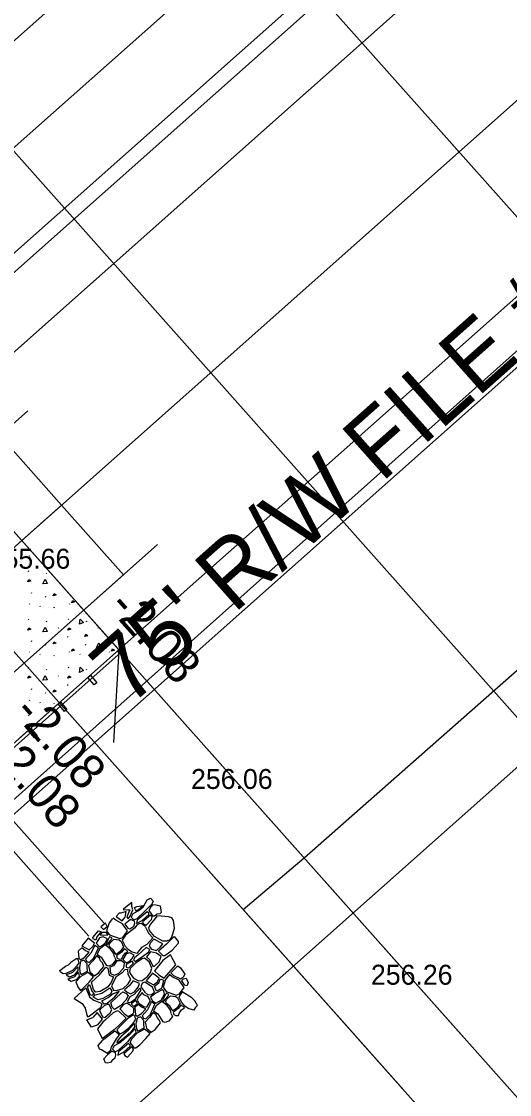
# Model space of a CAD drawing. Extents: x 49683 to 58852, y 49525 to 54803.
# Drawn here: x 53475.3 to 53548.7, y 51366.9 to 51528.4 of the extents above; entities that cross this region are included whole.
import ezdxf

# ---------------------------------------------------------------- set-up
doc = ezdxf.new("R2010")
doc.units = 0
for name, color, linetype in [('Level 1', 7, 'Continuous'), ('Level 11', 7, 'Continuous'), ('Level 13', 7, 'Continuous'), ('Level 15', 7, 'Continuous'), ('Level 16', 7, 'Continuous'), ('Level 19', 7, 'Continuous'), ('Level 20', 7, 'Continuous'), ('Level 25', 7, 'Continuous'), ('Level 27', 7, 'Continuous'), ('Level 29', 7, 'Continuous'), ('Level 3', 7, 'Continuous'), ('Level 32', 7, 'Continuous'), ('Level 33', 7, 'Continuous'), ('Level 5', 7, 'Continuous'), ('Level 50', 7, 'Continuous'), ('Level 53', 7, 'Continuous'), ('Level 61', 7, 'Continuous'), ('Level 63', 7, 'Continuous'), ('Level 8', 7, 'Continuous')]:
    doc.layers.add(name, color=color, linetype=linetype)

msp = doc.modelspace()

# ---------------------------------------------------------------- linework, layer by layer
at = {"layer": 'Level 1'}
msp.add_line((52544.81, 50683.3), (55534.58, 53340.86), dxfattribs=at)
at = {"layer": 'Level 11'}
msp.add_line((53245.86, 51207.55), (53944.24, 51830.77), dxfattribs=at)
at = {"layer": 'Level 13'}
msp.add_line((53681.55, 51593.39), (53435.6, 51374.77), dxfattribs=at)
at = {"layer": 'Level 15'}
for p, q in [((53460.73, 51466.68), (53909.18, 51865.3)), ((53938.41, 51832.41), (53489.97, 51433.79)), ((53460.73, 51466.68), (53489.97, 51433.79)), ((53476.47, 51448), (53476.52, 51447.91)), ((53476.36, 51445.58), (53476.42, 51445.71)), ((53479.07, 51445.26), (53479.13, 51445.39)), ((53476.82, 51442.31), (53476.88, 51442.43)), ((53478.93, 51441.74), (53478.99, 51441.86)), ((53476.47, 51440.75), (53476.52, 51440.67)), ((53478.08, 51440.4), (53478.14, 51440.32)), ((53480.2, 51440.13), (53480.25, 51440.25)), ((53482.47, 51440.75), (53482.52, 51440.67)), ((53484.08, 51440.4), (53484.14, 51440.32)), ((53476.36, 51438.34), (53476.42, 51438.46)), ((53482.36, 51438.34), (53482.42, 51438.46)), ((53479.07, 51438.02), (53479.13, 51438.14)), ((53480.81, 51437.13), (53480.86, 51437.05)), ((53485.07, 51438.02), (53485.13, 51438.14)), ((53486.81, 51437.13), (53486.86, 51437.05)), ((53476.82, 51435.06), (53476.88, 51435.19)), ((53482.21, 51435.8), (53482.22, 51435.68)), ((53488.21, 51435.77), (53488.22, 51435.68)), ((53489.97, 51433.79), (53475.02, 51420.51)), ((53476.47, 51433.51), (53476.52, 51433.43)), ((53478.93, 51434.5), (53478.99, 51434.62)), ((53482.47, 51433.51), (53482.52, 51433.43)), ((53484.93, 51434.5), (53484.99, 51434.62)), ((53488.47, 51433.51), (53488.52, 51433.43)), ((53489.97, 51433.79), (53489.14, 51419.82)), ((53478.08, 51433.16), (53478.14, 51433.07)), ((53480.2, 51432.89), (53480.25, 51433.01)), ((53484.08, 51433.16), (53484.14, 51433.07)), ((53486.2, 51432.89), (53486.25, 51433.01)), ((53476.36, 51431.1), (53476.42, 51431.22)), ((53479.07, 51430.78), (53479.13, 51430.9)), ((53482.36, 51431.1), (53482.42, 51431.22)), ((53485.07, 51430.78), (53485.13, 51430.9)), ((53480.81, 51429.89), (53480.86, 51429.81)), ((53482.21, 51428.56), (53482.22, 51428.43)), ((53476.82, 51427.82), (53476.88, 51427.95)), ((53478.93, 51427.25), (53478.99, 51427.38)), ((53476.47, 51426.27), (53476.52, 51426.18)), ((53478.08, 51425.91), (53478.14, 51425.83)), ((53480.2, 51425.64), (53480.25, 51425.77)), ((53476.36, 51423.85), (53476.42, 51423.98))]:
    msp.add_line(p, q, dxfattribs=at)
for points in [[(53476.26, 51444.01), (53476.43, 51444.36), (53476.71, 51444.15), (53476.26, 51444.01)], [(53478.52, 51443.72), (53478.89, 51444.43), (53479.19, 51443.78), (53478.53, 51443.72)], [(53480.08, 51441.91), (53480.24, 51442.25), (53480.52, 51442.05), (53480.08, 51441.91)], [(53482.85, 51440.85), (53483.02, 51441.2), (53483.3, 51440.99), (53482.85, 51440.85)], [(53484.03, 51437.63), (53484.14, 51438.42), (53484.64, 51437.91), (53484.04, 51437.64)], [(53476.26, 51436.77), (53476.43, 51437.12), (53476.71, 51436.91), (53476.26, 51436.77)], [(53478.52, 51436.48), (53478.89, 51437.19), (53479.19, 51436.54), (53478.53, 51436.48)], [(53482.26, 51436.77), (53482.43, 51437.12), (53482.71, 51436.91), (53482.26, 51436.77)], [(53480.08, 51434.67), (53480.24, 51435.01), (53480.52, 51434.8), (53480.08, 51434.67)], [(53484.82, 51435.78), (53484.98, 51436.13), (53485.26, 51435.92), (53484.82, 51435.78)], [(53482.85, 51433.61), (53483.02, 51433.95), (53483.3, 51433.75), (53482.85, 51433.61)], [(53486.58, 51434.15), (53486.96, 51434.86), (53487.25, 51434.21), (53486.6, 51434.15)], [(53488.85, 51433.61), (53489.02, 51433.95), (53489.3, 51433.75), (53488.85, 51433.61)], [(53484.03, 51430.39), (53484.14, 51431.18), (53484.64, 51430.67), (53484.04, 51430.39)], [(53476.26, 51429.53), (53476.43, 51429.88), (53476.71, 51429.67), (53476.26, 51429.53)], [(53478.52, 51429.24), (53478.89, 51429.95), (53479.19, 51429.29), (53478.53, 51429.24)], [(53482.26, 51429.53), (53482.43, 51429.88), (53482.71, 51429.67), (53482.26, 51429.53)], [(53480.08, 51427.42), (53480.24, 51427.77), (53480.52, 51427.56), (53480.08, 51427.42)], [(53476.26, 51422.29), (53476.43, 51422.63), (53476.71, 51422.42), (53476.26, 51422.29)]]:
    msp.add_lwpolyline(points, dxfattribs=at)
at = {"layer": 'Level 16'}
for p, q in [((53490.99, 51395.05), (53490.58, 51394.7)), ((53490.58, 51394.7), (53491.31, 51394.67)), ((53491.91, 51395.78), (53490.99, 51395.05)), ((53491.31, 51394.67), (53491.59, 51394.67)), ((53491.59, 51394.67), (53491.47, 51394.29)), ((53491.63, 51393.69), (53492.04, 51394.67)), ((53491.88, 51395.18), (53491.91, 51395.78)), ((53492.04, 51394.67), (53491.88, 51395.18)), ((53489.98, 51394.13), (53489.54, 51393.66)), ((53489.54, 51393.66), (53490.43, 51393)), ((53490.24, 51394.13), (53489.98, 51394.13)), ((53491.03, 51394.39), (53490.24, 51394.13)), ((53490.43, 51393), (53490.9, 51393.53)), ((53490.9, 51393.53), (53491.03, 51394.39)), ((53491.47, 51394.29), (53491.15, 51393.6)), ((53491.15, 51393.6), (53491.37, 51393.31)), ((53491.37, 51393.31), (53491.63, 51393.69)), ((53487.12, 51390.83), (53487.5, 51391.3)), ((53487.62, 51390.8), (53487.12, 51390.83)), ((53487.5, 51391.3), (53487.97, 51391.3)), ((53488.28, 51390.83), (53487.62, 51390.8)), ((53487.97, 51391.3), (53488.28, 51390.83))]:
    msp.add_line(p, q, dxfattribs=at)
for points in [[(53493.59, 51395.04), (53494.22, 51396.16), (53494.73, 51396.4), (53495.11, 51395.98), (53494.89, 51395.51), (53493.83, 51394.39)], [(53493.59, 51395.04), (53493.01, 51394.55), (53492.06, 51394.04), (53491.8, 51393.54), (53492.22, 51393.14), (53492.69, 51393.35), (53493.83, 51394.39)], [(53492.39, 51394.78), (53492.34, 51394.88), (53492.28, 51395), (53492.71, 51395.16), (53493.61, 51395.29)], [(53492.39, 51394.76), (53492.45, 51394.63), (53492.5, 51394.51), (53492.9, 51394.71), (53493.61, 51395.29)], [(53493.57, 51395.26), (53493.5, 51395.2)], [(53495.08, 51395.45), (53494.74, 51395.09), (53494.44, 51394.55), (53494.8, 51394.03), (53495.01, 51393.75), (53495.32, 51393.73), (53495.66, 51394)], [(53495.08, 51395.45), (53495.56, 51395.42), (53496.16, 51395.24), (53496.26, 51394.62), (53496.3, 51394.27), (53496.09, 51394.04), (53495.66, 51394)], [(53489, 51393.34), (53488.47, 51392.7), (53488.11, 51391.51), (53488.54, 51390.89), (53490.08, 51390.32), (53490.56, 51390.51), (53491.26, 51391.5), (53490.49, 51392.57), (53489.48, 51393.1), (53489.11, 51393.39)], [(53497.32, 51390.02), (53497.14, 51389.94), (53496.55, 51389.94), (53495.29, 51390.63), (53494.58, 51391.55), (53494.46, 51392), (53494.7, 51392.45), (53495.4, 51393.28)], [(53495.41, 51393.3), (53495.77, 51393.74)], [(53497.32, 51390.02), (53497.52, 51390.1), (53497.93, 51390.52), (53498.32, 51391.9), (53498.16, 51393.06), (53497.92, 51393.46), (53497.44, 51393.6), (53495.77, 51393.74)], [(53493.91, 51392.17), (53493.37, 51392.58), (53493.01, 51392.57), (53492.66, 51392.36), (53492.31, 51391.92), (53490.96, 51390.82), (53490.45, 51390.08), (53490.92, 51389.18)], [(53493.93, 51392.14), (53494.42, 51391.12), (53495.07, 51390.45), (53494.17, 51389.42), (53493.38, 51388.97), (53492.65, 51388.06), (53491.86, 51388.31), (53491.37, 51388.68), (53490.95, 51389.16)], [(53497.12, 51389.49), (53498.28, 51390.62), (53498.87, 51389.87), (53498.85, 51389.58), (53497.95, 51388.57)], [(53489.31, 51387.56), (53489.21, 51388.06), (53488.71, 51388.75), (53487.9, 51389.39), (53487.03, 51388.74), (53486.67, 51387.97), (53487.3, 51387.52), (53488.06, 51386.33)], [(53497.12, 51389.49), (53495.89, 51388.42), (53496.58, 51387.77), (53496.87, 51387.77), (53497.95, 51388.57)], [(53483, 51385.51), (53483.74, 51386.32), (53483.96, 51386.7), (53483.82, 51387.16), (53483.62, 51387.34), (53482.74, 51386.75), (53482.37, 51386.4)], [(53489.32, 51387.53), (53489.48, 51387.13), (53488.95, 51386.4), (53488.41, 51386.2), (53488.09, 51386.3)], [(53483, 51385.51), (53481.99, 51385.09), (53481.56, 51385), (53481.17, 51385.29), (53481.07, 51385.54), (53481.93, 51386.18), (53482.37, 51386.4)], [(53483.25, 51384.82), (53482.53, 51384.54), (53482.26, 51384.69), (53482.08, 51384.92), (53483.02, 51385.25)], [(53483.02, 51385.25), (53483.76, 51386.06), (53483.8, 51385.53), (53483.25, 51384.82)], [(53483.51, 51384.14), (53484.03, 51384.69), (53484, 51384.99), (53483.85, 51385.25), (53483.23, 51384.56)], [(53484.17, 51382.54), (53484.57, 51382.87), (53485.5, 51383.78), (53486.13, 51384.56), (53485.3, 51385.21), (53484.22, 51384.61), (53483.47, 51383.83)], [(53497.77, 51385.18), (53498.82, 51386.24), (53499.2, 51385.94), (53499.85, 51384.98), (53499.61, 51384.52)], [(53497.77, 51385.18), (53498.17, 51384.79), (53499.2, 51384.25), (53499.63, 51384.54)], [(53483.51, 51384.14), (53482.8, 51383.87), (53482.53, 51384.02), (53482.35, 51384.25), (53483.23, 51384.56)], [(53483.47, 51383.83), (53483.81, 51382.95), (53484.17, 51382.54)], [(53499.68, 51384.26), (53499.35, 51383.99), (53499.79, 51383.38), (53500.24, 51383.25)], [(53499.68, 51384.26), (53500.08, 51384.39), (53500.36, 51383.7), (53500.24, 51383.25)], [(53485, 51382.91), (53483.23, 51381.29), (53484.45, 51380.56), (53484.87, 51379.87), (53485.11, 51378.8), (53485.29, 51378.56), (53485.56, 51378.64)], [(53485, 51382.91), (53485.55, 51381.57), (53486.17, 51381.05), (53487.18, 51380.66), (53487.39, 51380.44), (53487.17, 51379.93), (53485.56, 51378.64)], [(53499.49, 51382.33), (53498.96, 51381.57), (53499.44, 51380.67)], [(53501.45, 51379.9), (53501.76, 51380.24), (53501.38, 51380.98), (53500.94, 51381.4), (53499.49, 51382.33)], [(53497.82, 51379.05), (53497.72, 51379.55), (53497.22, 51380.24), (53496.41, 51380.88), (53495.54, 51380.23), (53495.18, 51379.46), (53495.81, 51379), (53496.57, 51377.81)], [(53501.45, 51379.9), (53501.17, 51379.54), (53500.37, 51379.8), (53499.89, 51380.17), (53499.46, 51380.65)], [(53486.81, 51377.35), (53487.48, 51378.2), (53486.68, 51379.21), (53486.03, 51378.43)], [(53489.34, 51376.72), (53490.03, 51377.35), (53491.07, 51378.37), (53490, 51379.35), (53489.68, 51379.44), (53489.08, 51379.15), (53487.94, 51378.11)], [(53497.83, 51379.02), (53498, 51378.62), (53497.46, 51377.89), (53496.92, 51377.69), (53496.6, 51377.79)], [(53486.81, 51377.35), (53485.84, 51377.01), (53485.15, 51378.09), (53486.03, 51378.43)], [(53487.92, 51378.09), (53487.55, 51377.77), (53486.72, 51376.74), (53487.43, 51375.27), (53489.32, 51376.7)], [(53490.37, 51375.7), (53491.4, 51376.6), (53492.27, 51377.54), (53492.31, 51377.02), (53491.8, 51376.36), (53491.28, 51375.88), (53490.69, 51375.36)], [(53488.14, 51373.1), (53488.71, 51373.47), (53488.85, 51374), (53489.6, 51375.22), (53490.03, 51375.82), (53489.36, 51376.4), (53487.47, 51374.99)], [(53490.8, 51375.22), (53490.2, 51374.71), (53489.24, 51374.2), (53488.98, 51373.7), (53489.4, 51373.3), (53489.88, 51373.51), (53491.25, 51374.77)], [(53490.34, 51375.68), (53489.83, 51375.08), (53489.63, 51374.79), (53489.68, 51374.66), (53490.09, 51374.87), (53490.67, 51375.35)], [(53491.28, 51374.79), (53491.82, 51375.42), (53492.54, 51376.18), (53492.51, 51376.48), (53492.36, 51376.74), (53491.55, 51375.83), (53490.82, 51375.25)], [(53488.14, 51373.1), (53487.35, 51373.59), (53487.04, 51373.67), (53486.82, 51374.26), (53487.47, 51374.99)], [(53491.26, 51372.5), (53492.04, 51373.36), (53492.16, 51373.74), (53491.91, 51374.03), (53490.71, 51373), (53490.83, 51372.73), (53491.26, 51372.5)], [(53488.98, 51372.09), (53488.68, 51371.68), (53488.24, 51371.58), (53487.93, 51371.65), (53487.71, 51372.25), (53488.25, 51372.85)], [(53488.98, 51372.09), (53489.4, 51372.37), (53489.52, 51372.81), (53489.46, 51373.12), (53488.87, 51373.36), (53488.25, 51372.85)]]:
    msp.add_lwpolyline(points, dxfattribs=at)
for points in [[(53490.84, 51392.51), (53491.28, 51391.89), (53491.6, 51391.8), (53492.21, 51392.21), (53492.34, 51392.65), (53492.28, 51392.96), (53491.69, 51393.21)], [(53494.23, 51394.37), (53492.73, 51393.12), (53492.59, 51392.62), (53493.47, 51393.05), (53494.48, 51393.97), (53494.47, 51394.13)], [(53494.73, 51393.87), (53493.53, 51392.84), (53493.65, 51392.57), (53494.08, 51392.34), (53494.86, 51393.2), (53494.97, 51393.58)], [(53487.31, 51391.42), (53486.65, 51390.59), (53486.5, 51390.1), (53486.09, 51390.29), (53486.05, 51390.51), (53486.87, 51391.52)], [(53487.93, 51392.63), (53487.24, 51392.09), (53487.65, 51391.7), (53488.2, 51392.16)], [(53485.34, 51390.41), (53484.37, 51389.24), (53485.47, 51388.63), (53486.06, 51389.12), (53486.3, 51389.64)], [(53488.23, 51390.27), (53487.57, 51390.59), (53487.04, 51390.46), (53486.55, 51389.62), (53487.04, 51389.11), (53487.57, 51389.38), (53487.92, 51389.76)], [(53488.55, 51390.6), (53488.01, 51389.5), (53488.19, 51389.44), (53488.79, 51390.14), (53488.97, 51390.43)], [(53490.66, 51389.11), (53490.16, 51388.38), (53489.56, 51387.95), (53489.12, 51388.66), (53488.55, 51389.13), (53488.49, 51389.42), (53488.67, 51389.72), (53489.2, 51390.23), (53490.02, 51390.12), (53490.28, 51389.91)], [(53496.55, 51389.56), (53495.21, 51390.23), (53494.64, 51389.64), (53494.51, 51389.18), (53494.88, 51388.73), (53495.61, 51388.56), (53496.22, 51389.09)], [(53484.37, 51388.94), (53483.82, 51388.46), (53483.95, 51387.36), (53484.19, 51387.15), (53484.83, 51387.54), (53485.5, 51388.26), (53484.95, 51388.49)], [(53486.36, 51389.3), (53485.73, 51388.14), (53484.94, 51387.23), (53485.13, 51386.86), (53485.48, 51386.75), (53486.18, 51387.44), (53486.87, 51388.96)], [(53490.8, 51388.86), (53490.37, 51388.3), (53489.59, 51387.72), (53489.7, 51387.39), (53490.02, 51387.24), (53490.41, 51387.26), (53490.54, 51387.64), (53490.88, 51388.13), (53491.3, 51388.4)], [(53492.24, 51387.83), (53491.58, 51388.16), (53491.05, 51388.02), (53490.56, 51387.18), (53491.05, 51386.68), (53491.58, 51386.94), (53491.93, 51387.33)], [(53494.63, 51388.67), (53494.05, 51388.99), (53492.83, 51387.84), (53492.36, 51387.47), (53492.17, 51387.15), (53492.42, 51386.9), (53493.51, 51387.64), (53494.44, 51388.33)], [(53496.3, 51387.65), (53495.61, 51388.14), (53494.72, 51388.34), (53494.12, 51387.57), (53494.63, 51387.11), (53495.08, 51386.16), (53495.31, 51386.16), (53495.99, 51386.84)], [(53484.7, 51387.08), (53484.19, 51386.86), (53484.01, 51386.03), (53484.09, 51385.26), (53484.27, 51384.92), (53485.25, 51385.4), (53485.18, 51385.98), (53485.2, 51386.52)], [(53486.57, 51387.72), (53486.05, 51386.99), (53485.38, 51386.27), (53485.59, 51385.34), (53486.3, 51384.73), (53486.91, 51385.17), (53487.71, 51386.14), (53487.47, 51386.69), (53487.18, 51386.98), (53487.04, 51387.37)], [(53489.66, 51386.99), (53489.13, 51386.22), (53488.6, 51386.01), (53488.7, 51385.06), (53489.26, 51384.84), (53489.9, 51385.08), (53490.7, 51385.92), (53490.79, 51386.62), (53490.33, 51387)], [(53491.93, 51386.95), (53491.05, 51386.41), (53491.07, 51386.05), (53491.45, 51385.95), (53492.15, 51386.65)], [(53493.83, 51387.36), (53493.48, 51387.29), (53492.41, 51386.6), (53491.63, 51385.82), (53491.54, 51385.37), (53491.66, 51385.05), (53492.15, 51384.36), (53492.91, 51383.97), (53493.48, 51384.04), (53494.24, 51384.62), (53494.69, 51385.2), (53494.89, 51385.86), (53494.51, 51386.83)], [(53497.73, 51387.88), (53496.59, 51387.05), (53495.3, 51385.45), (53495.97, 51384.85), (53496.79, 51384.35), (53498.54, 51386.38)], [(53488.01, 51386.05), (53488.28, 51385.88), (53488.5, 51384.82), (53489.17, 51384.56), (53488.77, 51383.7), (53488.24, 51383.04), (53487.12, 51382.36), (53486.48, 51382.25), (53486.12, 51382.67), (53485.83, 51383.75), (53487.05, 51384.86)], [(53490.87, 51385.65), (53490.47, 51385.15), (53489.53, 51384.57), (53488.83, 51383.23), (53489.17, 51382.59), (53489.61, 51382.51), (53490.59, 51382.84), (53491.33, 51383.52), (53491.75, 51384.17), (53491.35, 51384.91), (53491.31, 51385.67)], [(53495.03, 51385.13), (53494.06, 51383.96), (53495.16, 51383.35), (53495.75, 51383.84), (53496, 51384.36)], [(53499.77, 51382.99), (53499, 51384.06), (53497.99, 51384.59), (53497.58, 51384.91), (53496.98, 51384.19), (53496.62, 51383), (53497.05, 51382.37), (53498.59, 51381.81), (53499.07, 51382)], [(53485.53, 51383.4), (53485.91, 51382.41), (53486.24, 51382.03), (53485.87, 51381.77), (53485.66, 51381.85), (53485.22, 51383.08)], [(53492.11, 51383.98), (53491.51, 51383.24), (53490.81, 51382.62), (53491.21, 51382.26), (53491.69, 51382.01), (53492.3, 51382.33), (53492.85, 51383), (53493.07, 51383.56)], [(53495.33, 51382.27), (53495.02, 51383.03), (53493.85, 51383.76), (53493.46, 51383.61), (53493.26, 51383.09), (53493.84, 51382.25), (53494.32, 51381.84), (53494.86, 51381.92)], [(53496.23, 51384.25), (53496.66, 51384.09), (53496.38, 51382.8), (53495.63, 51382.42), (53495.3, 51383.19), (53495.95, 51383.67)], [(53488.61, 51382.94), (53488.91, 51382.41), (53488.68, 51381.94), (53487.56, 51381.33), (53486.83, 51381.13), (53486.07, 51381.49), (53486.37, 51381.85), (53487.37, 51382.13)], [(53490.02, 51382.38), (53489.11, 51382.02), (53488.4, 51381.48), (53487.34, 51380.92), (53487.7, 51380.52), (53488.18, 51380.6), (53489.36, 51381.55)], [(53490.55, 51382.32), (53491.05, 51382.06), (53491.34, 51381.7), (53491.01, 51381.07), (53490.18, 51380.21), (53489.28, 51379.64), (53488.95, 51380.03), (53488.74, 51380.64), (53489.71, 51381.54)], [(53493.1, 51382.87), (53492.26, 51381.92), (53491.57, 51381.49), (53491.26, 51380.86), (53491.5, 51380.67), (53491.82, 51380.79), (53492.48, 51381.3), (53493.3, 51382.61)], [(53494.69, 51380.95), (53494.34, 51381.55), (53493.73, 51381.84), (53493.46, 51382.19), (53492.87, 51381.48), (53492.73, 51381.05), (53492.95, 51380.63), (53493.73, 51380.1), (53494.17, 51380.03)], [(53496.49, 51382.64), (53495.52, 51382.12), (53494.7, 51381.49), (53495, 51380.94), (53495.53, 51380.61), (53496.31, 51381.08), (53496.82, 51381.95), (53496.74, 51382.48)], [(53497.06, 51382.09), (53496.52, 51380.99), (53496.7, 51380.93), (53497.31, 51381.63), (53497.48, 51381.92)], [(53499.17, 51380.6), (53498.68, 51379.86), (53498.07, 51379.44), (53497.63, 51380.15), (53497.06, 51380.62), (53497, 51380.9), (53497.18, 51381.21), (53497.71, 51381.71), (53498.53, 51381.6), (53498.79, 51381.4)], [(53488.43, 51380.46), (53487.78, 51380.24), (53487.12, 51379.64), (53487.03, 51379.5), (53487.49, 51378.53), (53487.83, 51378.44), (53488.64, 51379.15), (53488.89, 51379.58)], [(53492.2, 51379.21), (53492.18, 51379.79), (53491.67, 51380.29), (53491.12, 51380.63), (53490.59, 51380.35), (53490.12, 51379.74), (53490.74, 51379.03), (53491.33, 51378.6), (53491.96, 51378.93)], [(53492.48, 51381.03), (53491.79, 51380.49), (53492.2, 51380.1), (53492.75, 51380.56)], [(53492.88, 51380.43), (53492.33, 51379.95), (53492.47, 51378.85), (53492.7, 51378.64), (53493.34, 51379.03), (53494.01, 51379.75), (53493.46, 51379.98)], [(53494.87, 51380.79), (53494.24, 51379.62), (53493.45, 51378.72), (53493.64, 51378.35), (53494, 51378.24), (53494.69, 51378.93), (53495.38, 51380.45)], [(53499.31, 51380.35), (53498.88, 51379.79), (53498.1, 51379.2), (53498.22, 51378.88), (53498.53, 51378.73), (53498.92, 51378.74), (53499.06, 51379.13), (53499.39, 51379.62), (53499.81, 51379.89)], [(53492.13, 51378.83), (53491.25, 51378.24), (53490.34, 51377.37), (53489.64, 51376.6), (53489.85, 51376.26), (53490.15, 51376), (53490.56, 51376.17), (53491.4, 51376.87), (53492.25, 51377.81), (53492.48, 51378.19), (53492.33, 51378.65)], [(53493.21, 51378.57), (53492.7, 51378.35), (53492.52, 51377.52), (53492.6, 51376.75), (53492.79, 51376.41), (53493.76, 51376.89), (53493.69, 51377.47), (53493.72, 51378)], [(53495.08, 51379.21), (53494.57, 51378.47), (53493.89, 51377.76), (53494.11, 51376.83), (53494.81, 51376.22), (53495.42, 51376.65), (53496.22, 51377.63), (53495.98, 51378.17), (53495.69, 51378.46), (53495.55, 51378.86)], [(53494.64, 51376.05), (53493.81, 51376.7), (53492.73, 51376.1), (53491.92, 51375.25), (53491.62, 51374.71), (53491.98, 51374.19), (53492.19, 51373.91), (53492.5, 51373.89), (53493.09, 51374.36), (53494.01, 51375.27)], [(53491.41, 51374.53), (53489.91, 51373.28), (53489.78, 51372.78), (53490.65, 51373.21), (53491.67, 51374.13), (53491.65, 51374.29)]]:
    msp.add_lwpolyline(points, close=True, dxfattribs=at)
at = {"layer": 'Level 19'}
for p, q in [((52714.15, 50773.62), (54181.77, 52078.16)), ((53541.12, 51508.7), (53538.46, 51511.69))]:
    msp.add_line(p, q, dxfattribs=at)
at = {"layer": 'Level 20'}
for p, q in [((52704.85, 50784.08), (53476.26, 51469.77)), ((52723.45, 50763.15), (53495.78, 51449.66))]:
    msp.add_line(p, q, dxfattribs=at)
at = {"layer": 'Level 27'}
for p, q in [((53467.54, 51413.86), (53489.97, 51433.79)), ((53467.88, 51413.49), (53490.3, 51433.42))]:
    msp.add_line(p, q, dxfattribs=at)
for points in [[(53491.12, 51432.8), (53490.74, 51432.48), (53489.77, 51433.63), (53490.16, 51433.95)], [(53486.63, 51428.82), (53486.25, 51428.5), (53485.29, 51429.65), (53485.67, 51429.97)], [(53482.15, 51424.83), (53481.77, 51424.51), (53480.8, 51425.66), (53481.19, 51425.98)], [(53477.67, 51420.84), (53477.28, 51420.52), (53476.32, 51421.67), (53476.7, 51422)]]:
    msp.add_lwpolyline(points, close=True, dxfattribs=at)
at = {"layer": 'Level 29'}
for p, q in [((52714.15, 50773.62), (54181.77, 52078.16)), ((53541.12, 51508.7), (53538.46, 51511.69))]:
    msp.add_line(p, q, dxfattribs=at)
at = {"layer": 'Level 3'}
for p, q in [((53434.09, 51489.84), (53883.27, 51889.18)), ((53449.72, 51471.81), (53898.74, 51870.57))]:
    msp.add_line(p, q, dxfattribs=at)
at = {"layer": 'Level 33'}
msp.add_line((52763.97, 50717.56), (53711.35, 51559.67), dxfattribs=at)
at = {"layer": 'Level 5'}
msp.add_line((53900.07, 51869.4), (53451.19, 51470.16), dxfattribs=at)
at = {"layer": 'Level 50'}
for p, q in [((53461.4, 51598.39), (53620.85, 51419.01)), ((53424.03, 51565.17), (53583.47, 51385.79)), ((53375.7, 51562.35), (53575, 51338.12)), ((53386.66, 51531.95), (53546.1, 51352.57))]:
    msp.add_line(p, q, dxfattribs=at)
at = {"layer": 'Level 53'}
for p, q in [((53408.91, 51524.98), (53541.79, 51375.5)), ((53399.94, 51517.01), (53532.82, 51367.52))]:
    msp.add_line(p, q, dxfattribs=at)
at = {"layer": 'Level 61'}
for p, q in [((53517.82, 51402.46), (53967.76, 51799.4)), ((53508.67, 51394.69), (53517.82, 51402.46))]:
    msp.add_line(p, q, dxfattribs=at)
at = {"layer": 'Level 63'}
for p, q in [((53472.03, 51466.02), (53481.33, 51455.55)), ((53481.33, 51455.55), (53460.4, 51436.95)), ((53460.4, 51436.95), (53481.33, 51455.55)), ((53481.33, 51455.55), (53490.63, 51445.09)), ((53490.63, 51445.09), (53469.7, 51426.49))]:
    msp.add_line(p, q, dxfattribs=at)
at = {"layer": 'Level 8'}
for p, q in [((53468.29, 51414.53), (53487.72, 51392.67)), ((53466.05, 51412.53), (53485.44, 51390.71))]:
    msp.add_line(p, q, dxfattribs=at)

# ---------------------------------------------------------------- texts
at = {"layer": 'Level 25'}
msp.add_text("75' R/W FILE # 408-B", height=10, rotation=41.6333, dxfattribs=at).set_placement((53491.41, 51425.05))
at = {"layer": 'Level 32'}
for s, p in [('255.66', (53470.38, 51446)), ('256.06', (53500.81, 51412.85)), ('256.26', (53527.87, 51383.39))]:
    msp.add_text(s, height=3, dxfattribs=at).set_placement(p)
at = {"layer": 'Level 63'}
for rotation, p in [(311.6332, (53488.16, 51440.19)), (311.6335, (53473.88, 51424.28)), (311.6332, (53470.11, 51418.35))]:
    msp.add_text('-2.08', height=5.25, rotation=rotation, dxfattribs=at).set_placement(p)

doc.saveas('drawing.dxf')
